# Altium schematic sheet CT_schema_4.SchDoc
size 556 x 419 mm
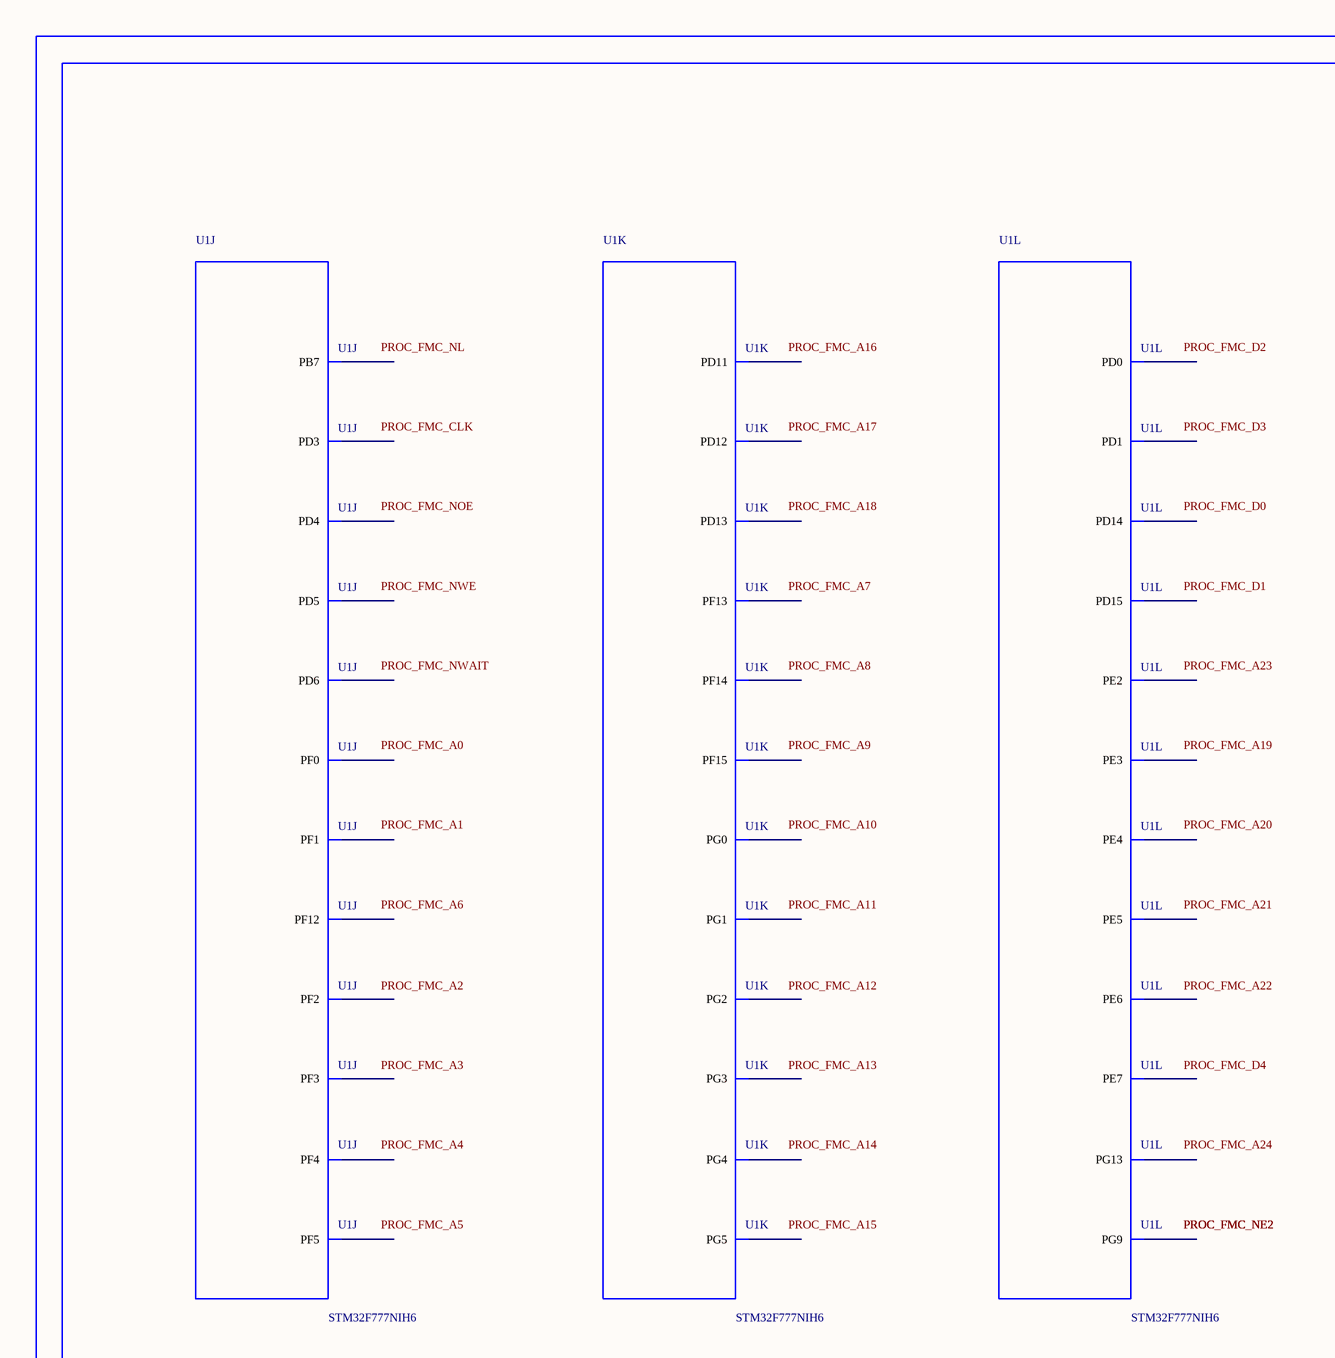
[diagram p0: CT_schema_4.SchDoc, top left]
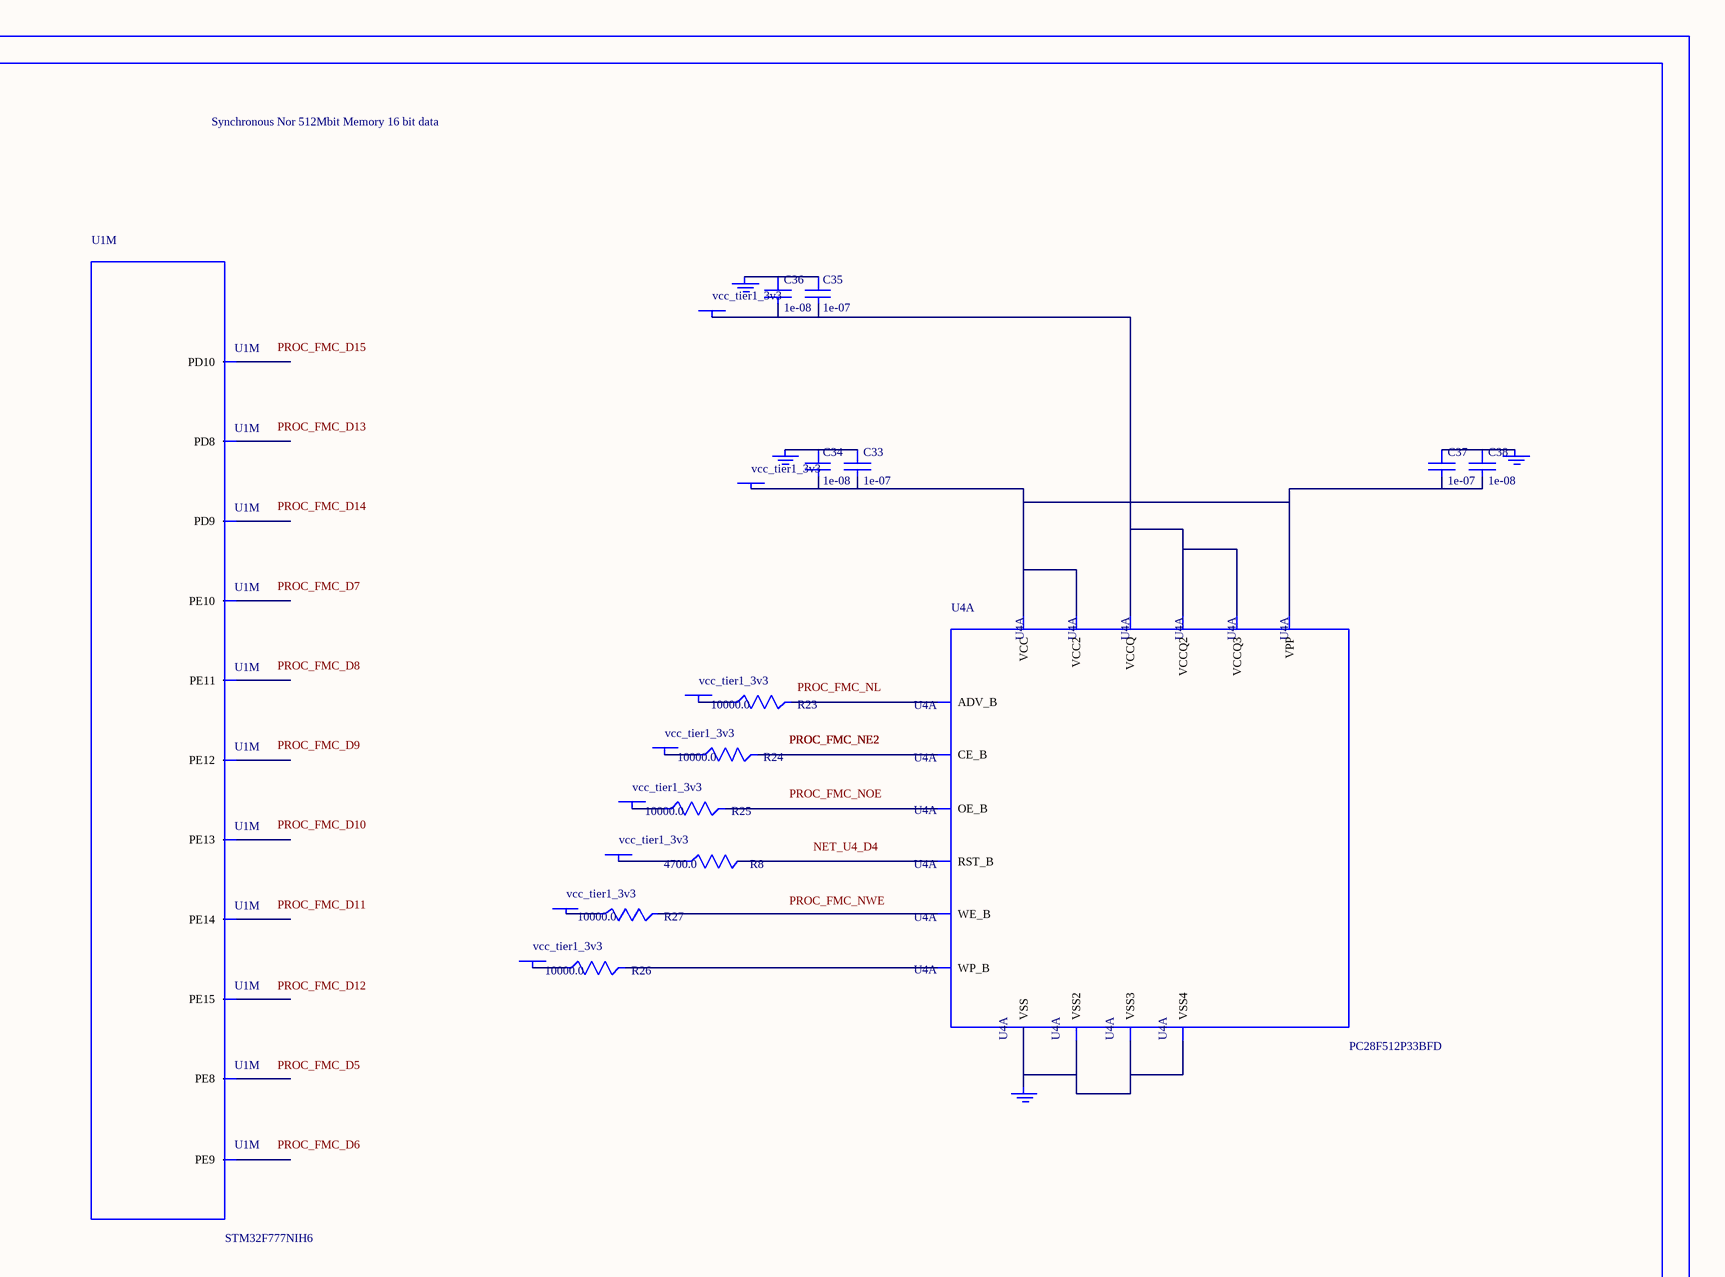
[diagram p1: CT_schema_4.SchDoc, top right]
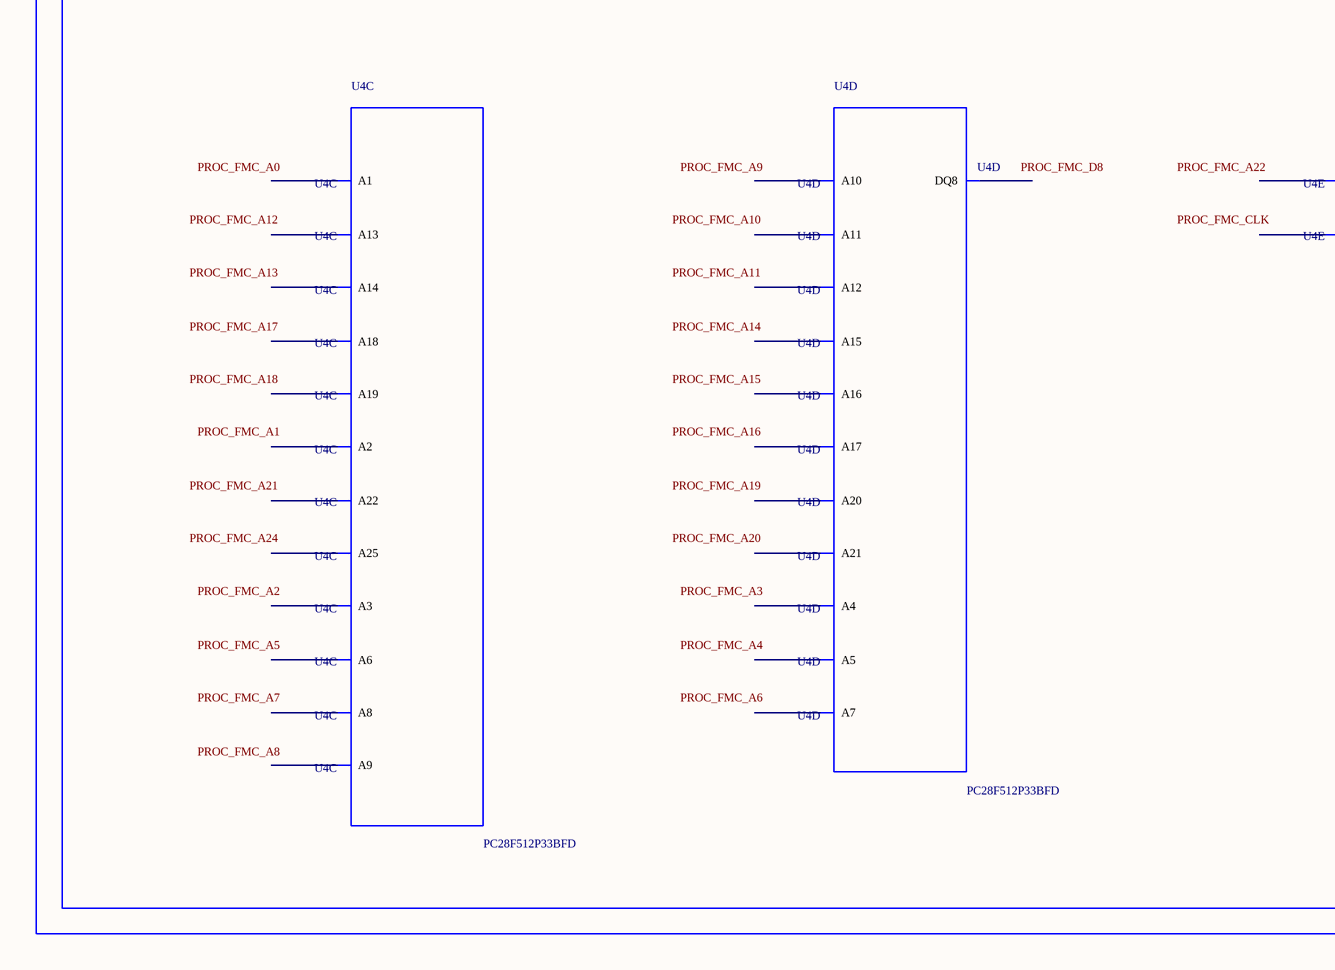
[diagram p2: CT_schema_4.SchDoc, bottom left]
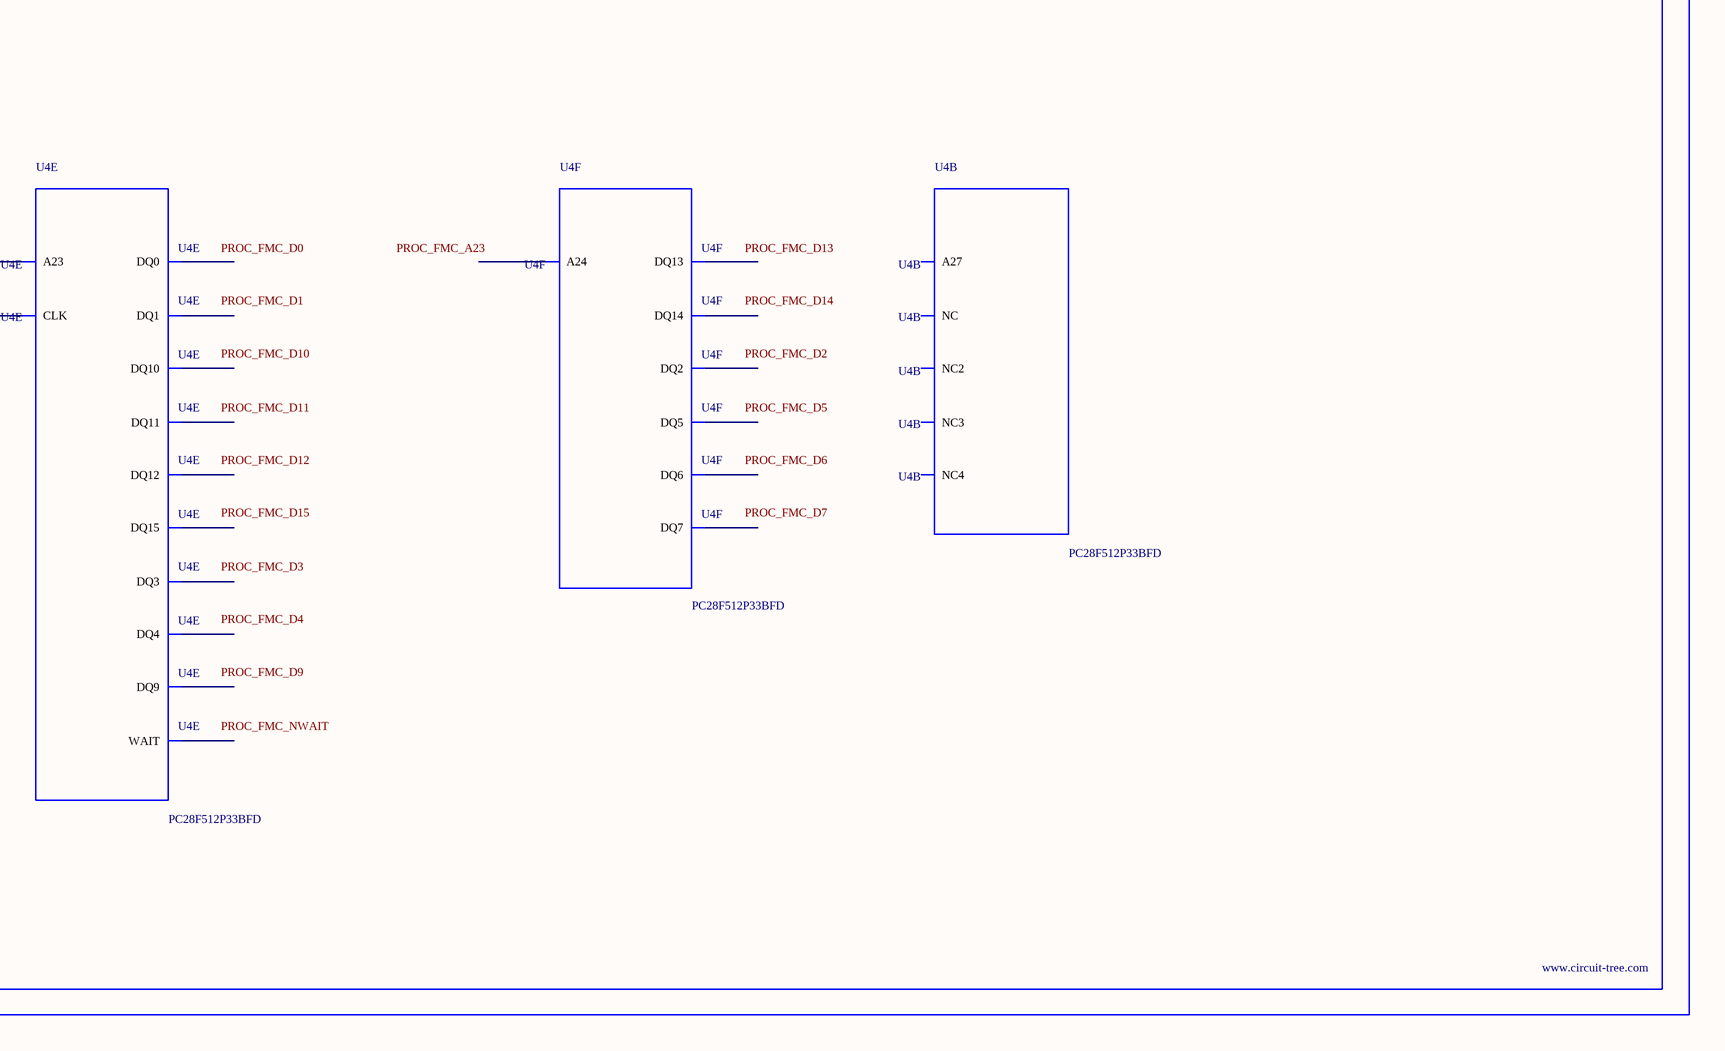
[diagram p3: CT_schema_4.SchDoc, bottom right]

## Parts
BORDER3  (no value)
C33  1e-07  [C0402]
C34  1e-08  [C0402]
C35  1e-07  [C0402]
C36  1e-08  [C0402]
C37  1e-07  [C0402]
C38  1e-08  [C0402]
GND_INSTANCE_3_0  (no value)
GND_INSTANCE_3_1  (no value)
GND_INSTANCE_3_2  (no value)
GND_INSTANCE_3_3  (no value)
POWER_INSTANCE_3_0  vcc_tier1_3v3
POWER_INSTANCE_3_1  vcc_tier1_3v3
POWER_INSTANCE_3_2  vcc_tier1_3v3
POWER_INSTANCE_3_3  vcc_tier1_3v3
POWER_INSTANCE_3_4  vcc_tier1_3v3
POWER_INSTANCE_3_5  vcc_tier1_3v3
POWER_INSTANCE_3_6  vcc_tier1_3v3
POWER_INSTANCE_3_7  vcc_tier1_3v3
R8  4700.0  [R0603]
R23  10000.0  [R0603]
R24  10000.0  [R0603]
R25  10000.0  [R0603]
R26  10000.0  [R0603]
R27  10000.0  [R0603]
U1  STM32F777NIH6  [TFBGA216]  (parts J,K,L,M of 15)
U4  PC28F512P33BFD  [PC28F512P33BFD]  (parts A,B,C,D,E,F of 6)

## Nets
NetC33_1: C33.1 C34.1 GND_INSTANCE_3_0.0(GND)
NetC33_2: C33.2 C34.2 C37.2 C38.2 POWER_INSTANCE_3_0.0(PWR) U4.A4(VPP) U4.A6(VCC) U4.H3(VCC2)
NetC35_1: C35.1 C36.1 GND_INSTANCE_3_1.0(GND)
NetC35_2: C35.2 C36.2 POWER_INSTANCE_3_1.0(PWR) U4.D5(VCCQ) U4.D6(VCCQ2) U4.G4(VCCQ3)
NetC37_1: C37.1 C38.1 GND_INSTANCE_3_2.0(GND)
NetGND_INSTANCE_3_3_0: GND_INSTANCE_3_3.0(GND) U4.B2(VSS) U4.H2(VSS2) U4.H4(VSS3) U4.H6(VSS4)
NetPOWER_INSTANCE_3_2_0: POWER_INSTANCE_3_2.0(PWR) R23.1
NetPOWER_INSTANCE_3_3_0: POWER_INSTANCE_3_3.0(PWR) R24.1
NetPOWER_INSTANCE_3_4_0: POWER_INSTANCE_3_4.0(PWR) R25.1
NetPOWER_INSTANCE_3_5_0: POWER_INSTANCE_3_5.0(PWR) R26.1
NetPOWER_INSTANCE_3_6_0: POWER_INSTANCE_3_6.0(PWR) R27.1
NetPOWER_INSTANCE_3_7_0: POWER_INSTANCE_3_7.0(PWR) R8.1
NetR8_2: R8.2 U4.D4(RST_B)
NetR23_2: R23.2 U4.F6(ADV_B)
NetR24_2: R24.2 U4.B4(CE_B)
NetR25_2: R25.2 U4.F8(OE_B)
NetR26_2: R26.2 U4.C6(WP_B)
NetR27_2: R27.2 U4.G8(WE_B)

Not connected (* = marked no-connect by the designer): U1 A1(PE4) A2(PE3) A3(PE2) B1(PE5) B2(PE6) B3(PG13) B5(PB7) B11(PD6) B12(PD0) C10(PD5) C11(PD3) C12(PD1) D2(PF0) D9(PG9) D11(PD4) E2(PF1) G2(PF2) H2(PF3) J2(PF4) K3(PF5) K13(PD15) K15(PD10) L12(PD14) L14(PD9) L15(PD8) M6(PF12) M7(PG1) M8(PF15) M10(PD12) M11(PD13) M12(PG3) M13(PG2) N6(PF13) N7(PG0) N9(PE8) N10(PD11) N11(PG5) N12(PG4) P6(PF14) P9(PE9) P10(PE11) P11(PE14) R8(PE7) R9(PE10) R10(PE12) R11(PE15) R12(PE13); U4 A1 A2(A6) A3(A8) A5(A13) A7(A18) A8(A22) B1(A2) B3(A9) B5(A14) B6(A25) B7(A19) B8(NC) C1(A3) C2(A7) C3(A10) C4(A12) C5(A15) C7(A20) C8(A21) D1(A4) D2(A5) D3(A11) D7(A16) D8(A17) E1(DQ8) E2(DQ1) E3(DQ9) E4(DQ3) E5(DQ4) E6(CLK) E7(DQ15) E8(NC2) F1(NC3) F2(DQ0) F3(DQ10) F4(DQ11) F5(DQ12) F7(WAIT) G1(A23) G2(NC4) G3(DQ2) G5(DQ5) G6(DQ6) G7(DQ14) H1(A27) H5(DQ13) H7(DQ7) H8(A24)

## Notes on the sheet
- Labels drawn without touching a wire or pin: NET_U4_D4, PROC_FMC_A0, PROC_FMC_A1, PROC_FMC_A2, PROC_FMC_A3, PROC_FMC_A4, PROC_FMC_A5, PROC_FMC_A6, PROC_FMC_A7, PROC_FMC_A8, PROC_FMC_A9, PROC_FMC_A10, PROC_FMC_A11, PROC_FMC_A12, PROC_FMC_A13, PROC_FMC_A14, PROC_FMC_A15, PROC_FMC_A16, PROC_FMC_A17, PROC_FMC_A18, PROC_FMC_A19, PROC_FMC_A20, PROC_FMC_A21, PROC_FMC_A22, PROC_FMC_A23, PROC_FMC_A24, PROC_FMC_CLK, PROC_FMC_D0, PROC_FMC_D1, PROC_FMC_D2, PROC_FMC_D3, PROC_FMC_D4, PROC_FMC_D5, PROC_FMC_D6, PROC_FMC_D7, PROC_FMC_D8, PROC_FMC_D9, PROC_FMC_D10, PROC_FMC_D11, PROC_FMC_D12, PROC_FMC_D13, PROC_FMC_D14, PROC_FMC_D15, PROC_FMC_NL, PROC_FMC_NOE, PROC_FMC_NWAIT, PROC_FMC_NWE

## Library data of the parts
BORDER3 = BORDER_PAGE3
C33 C35 C37 = C0402C104K3RACTU
C34 C36 C38 = C0402C103K3RAC
GND_INSTANCE_3_0-GND_INSTANCE_3_3 = GND
POWER_INSTANCE_3_0-POWER_INSTANCE_3_7 = PWR
R8 = RC0603JR-074K7L
R23-R27 = RC0603JR-0710KL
